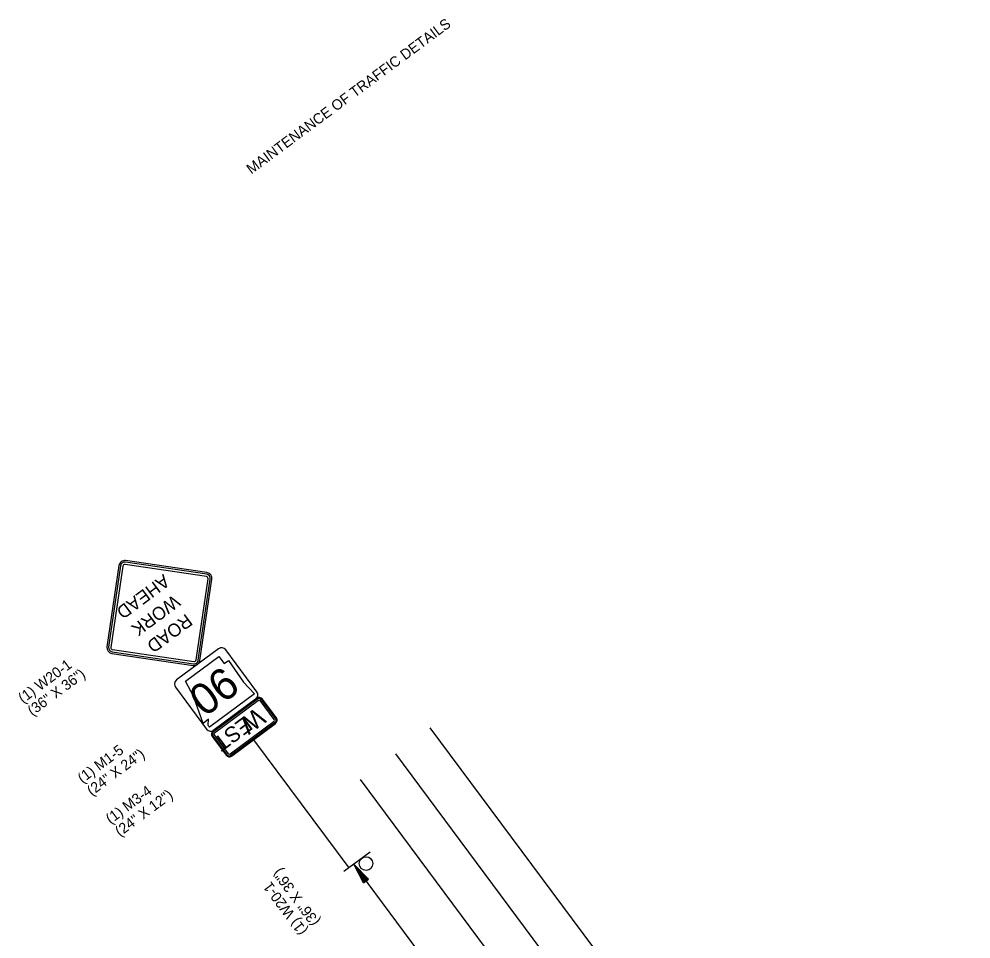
# Model space of a CAD drawing. Extents: x 998982 to 1000630, y 1875366 to 1876934.
# Drawn here: x 999809 to 1000357, y 1876405 to 1876934 of the extents above; entities that cross this region are included whole.
import ezdxf

# ---------------------------------------------------------------- set-up
doc = ezdxf.new("R2010")
doc.units = 0
for name, color, linetype in [('P_TC_Signs_Permanent', 7, 'Continuous'), ('P_TC_Signs_Temporary', 7, 'Continuous'), ('R_Border', 7, 'Continuous'), ('R_Border Prem', 7, 'Continuous'), ('R_Draft', 7, 'Continuous'), ('STAMP', 7, 'Continuous')]:
    doc.layers.add(name, color=color, linetype=linetype)

msp = doc.modelspace()

# ---------------------------------------------------------------- linework, layer by layer
at = {"layer": 'P_TC_Signs_Permanent'}
for p, q in [((999923.99, 1876571.53), (999899.9, 1876553.65)), ((999946.07, 1876546.82), (999928.18, 1876570.91)), ((999899.28, 1876549.45), (999917.16, 1876525.36)), ((999946.05, 1876543.07), (999920.76, 1876524.3)), ((999946.38, 1876542.62), (999921.09, 1876523.84)), ((999921.36, 1876524.74), (999945.45, 1876542.63)), ((999957.25, 1876531.77), (999949.2, 1876542.61)), ((999946.94, 1876541.87), (999921.65, 1876523.09)), ((999956.04, 1876530.88), (999947.99, 1876541.72)), ((999956.79, 1876531.44), (999948.75, 1876542.27)), ((999930.6, 1876511.05), (999955.89, 1876529.83)), ((999931.15, 1876510.3), (999956.44, 1876529.07)), ((999931.49, 1876509.84), (999956.78, 1876528.62)), ((999920.29, 1876521.15), (999928.34, 1876510.31)), ((999920.75, 1876521.48), (999928.79, 1876510.64)), ((999921.5, 1876522.04), (999929.55, 1876511.2))]:
    msp.add_line(p, q, dxfattribs=at)
msp.add_lwpolyline([(999918.84, 1876526.49), (999918.35, 1876526.83), (999917.99, 1876527.66), (999918.21, 1876531.02), (999915.06, 1876528.5), (999909.67, 1876544.33), (999905.03, 1876552.95), (999924.22, 1876567.08), (999927.2, 1876563.18), (999929.72, 1876564.87), (999938.43, 1876552.4), (999944.74, 1876545.74), (999919.62, 1876526.96), (999918.84, 1876526.49)], dxfattribs=at)
for centre, radius, start, end in [((999925.77, 1876569.12), 3, 36.5953, 126.5953), ((999901.69, 1876551.24), 3, 126.5953, 216.5953), ((999943.66, 1876545.04), 3, 306.5953, 36.5953), ((999947.39, 1876541.27), 2.25, 36.5953, 126.5953), ((999947.39, 1876541.27), 1.69, 36.5953, 126.5953), ((999947.39, 1876541.27), 0.75, 36.5953, 126.5953), ((999955.44, 1876530.43), 2.25, 306.5953, 36.5953), ((999955.44, 1876530.43), 0.75, 306.5953, 36.5953), ((999955.44, 1876530.43), 1.69, 306.5953, 36.5953), ((999919.57, 1876527.15), 3, 216.5953, 306.5953), ((999922.1, 1876522.49), 2.25, 126.5953, 216.5953), ((999922.1, 1876522.49), 1.69, 126.5953, 216.5953), ((999922.1, 1876522.49), 0.75, 126.5953, 216.5953), ((999930.15, 1876511.65), 2.25, 216.5953, 306.5953), ((999930.15, 1876511.65), 1.69, 216.5953, 306.5953), ((999930.15, 1876511.65), 0.75, 216.5953, 306.5953)]:
    msp.add_arc(centre, radius, start, end, dxfattribs=at)
at = {"layer": 'P_TC_Signs_Temporary'}
for p, q in [((999866.76, 1876619.44), (999859.85, 1876572.7)), ((999867.68, 1876619.3), (999860.78, 1876572.56)), ((999868.98, 1876619.11), (999862.07, 1876572.37)), ((999917, 1876613.15), (999870.26, 1876620.06)), ((999917.19, 1876614.45), (999870.45, 1876621.36)), ((999917.33, 1876615.38), (999870.59, 1876622.29)), ((999911.04, 1876565.13), (999917.95, 1876611.88)), ((999912.34, 1876564.94), (999919.25, 1876611.68)), ((999913.27, 1876564.8), (999920.18, 1876611.55)), ((999862.83, 1876569.79), (999909.57, 1876562.89)), ((999863.02, 1876571.09), (999909.77, 1876564.19)), ((999862.69, 1876568.87), (999909.44, 1876561.96))]:
    msp.add_line(p, q, dxfattribs=at)
for centre, radius, start, end in [((999870.09, 1876618.95), 3.38, 81.5953, 171.5953), ((999870.09, 1876618.95), 2.44, 81.5953, 171.5953), ((999870.09, 1876618.95), 1.13, 81.5953, 171.5953), ((999916.84, 1876612.04), 2.44, 351.5953, 81.5953), ((999916.84, 1876612.04), 3.38, 351.5953, 81.5953), ((999916.84, 1876612.04), 1.12, 351.5953, 81.5953), ((999863.19, 1876572.2), 3.38, 171.5953, 261.5953), ((999863.19, 1876572.2), 2.44, 171.5953, 261.5953), ((999863.19, 1876572.2), 1.12, 171.5953, 261.5953), ((999909.93, 1876565.3), 3.38, 261.5953, 351.5953), ((999909.93, 1876565.3), 2.44, 261.5953, 351.5953), ((999909.93, 1876565.3), 1.13, 261.5953, 351.5953)]:
    msp.add_arc(centre, radius, start, end, dxfattribs=at)
at = {"layer": 'R_Draft'}
for p, q in [((1000356.62, 1876107.48), (1000045.75, 1876526.13)), ((999944.13, 1876519.23), (999998.88, 1876445.51)), ((1000025.68, 1876511.22), (1000336.54, 1876092.57)), ((1000146.77, 1876306.21), (1000005.61, 1876496.32)), ((1000001.73, 1876447.62), (999996.03, 1876443.39)), ((1000120.96, 1876287.05), (1000001.73, 1876447.62)), ((1000007.42, 1876436.94), (1000001.73, 1876447.62)), ((1000010.3, 1876439.08), (1000001.73, 1876447.62)), ((1000007.66, 1876437.12), (1000002.92, 1876446.02)), ((1000010.06, 1876438.9), (1000002.92, 1876446.02)), ((1000009.82, 1876438.72), (1000004.15, 1876444.36)), ((1000007.9, 1876437.3), (1000004.15, 1876444.36)), ((1000008.15, 1876437.48), (1000005.33, 1876442.77)), ((1000009.58, 1876438.54), (1000005.33, 1876442.77)), ((1000009.33, 1876438.36), (1000006.54, 1876441.13)), ((1000008.4, 1876437.67), (1000006.54, 1876441.13)), ((1000007.42, 1876436.94), (1000010.3, 1876439.08)), ((1000009.09, 1876438.18), (1000007.74, 1876439.53)), ((1000008.64, 1876437.84), (1000007.74, 1876439.53))]:
    msp.add_line(p, q, dxfattribs=at)
at = {"layer": 'STAMP'}
msp.add_line((1000011.16, 1876454.63), (1000001.73, 1876447.61), dxfattribs=at)
msp.add_circle((1000008.79, 1876447.98), 3.92, dxfattribs=at)

# ---------------------------------------------------------------- texts
at = {"layer": 'P_TC_Signs_Permanent'}
for s, height, p in [('90', 18, (999926.7, 1876562.34)), ('EST', 9, (999939.1, 1876533.24)), ('W', 10.5, (999945.75, 1876538.18))]:
    msp.add_text(s, height=height, rotation=216.5953, dxfattribs=at).set_placement(p)
at = {"layer": 'P_TC_Signs_Temporary'}
for s, p in [('AHEAD', (999892.31, 1876614.79)), ('WORK', (999898.24, 1876602.97)), (' ROAD ', (999907.56, 1876593.68))]:
    msp.add_text(s, height=7.5, rotation=216.5953, dxfattribs=at).set_placement(p)
at = {"layer": 'R_Border'}
msp.add_text('MAINTENANCE OF TRAFFIC DETAILS', height=6, rotation=36.5953, dxfattribs=at).set_placement((999942.87, 1876844.35))
at = {"layer": 'R_Border Prem'}
for s, rotation, p in [('(1) W20-1', 36.5953, (999811.57, 1876539.93)), ('(36" X 36")', 36.5953, (999816.94, 1876532.7)), ('(1) M1-5', 36.5953, (999845.7, 1876493.96)), ('(24" X 24")', 36.5953, (999851.07, 1876486.73)), ('(1) M3-4', 36.5953, (999861.91, 1876470.48)), ('(24" X 12")', 36.5953, (999867.28, 1876463.25)), ('(36" X 36")', 126.5953, (999982.52, 1876414.82)), ('(1) W20-1', 126.5953, (999975.29, 1876409.45))]:
    msp.add_text(s, height=6, rotation=rotation, dxfattribs=at).set_placement(p)

doc.saveas('drawing.dxf')
